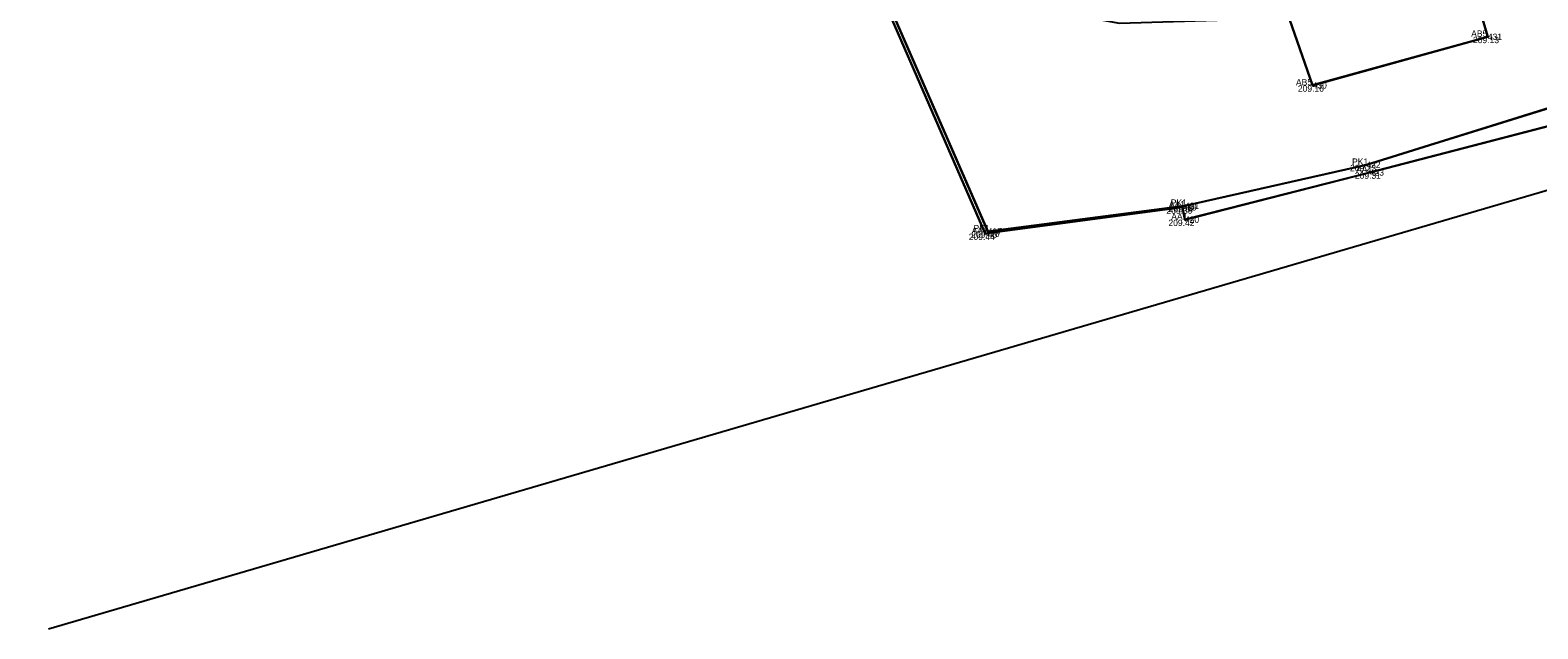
# Model space of a CAD drawing. Extents: x -262982 to -262706, y -1238714 to -1237093.
# Drawn here: x -262858.42 to -262811.08, y -1238714.26 to -1238695.45 of the extents above; entities that cross this region are included whole.
import ezdxf

# ---------------------------------------------------------------- set-up
doc = ezdxf.new("R2010")
doc.units = 0
for name, color, linetype in [('02_Oplotenie', 7, 'Continuous'), ('03_Asfalt', 7, 'Continuous'), ('08_Mimo_zelene', 7, 'Continuous'), ('10', 7, 'Continuous'), ('Groma (21)', 7, 'Continuous'), ('Groma (22)', 7, 'Continuous'), ('Groma (23)', 7, 'Continuous'), ('Groma (24)', 7, 'Continuous'), ('U001_Ostatné_plochy', 7, 'Continuous'), ('U001_Zeleň_mimo', 7, 'Continuous'), ('U001_Zeleň_vnútro', 7, 'Continuous')]:
    doc.layers.add(name, color=color, linetype=linetype)

msp = doc.modelspace()

# ---------------------------------------------------------------- linework, layer by layer
at = {"layer": '02_Oplotenie'}
msp.add_lwpolyline([(-262896.033, -1238537.323), (-262884.611, -1238562.768), (-262875.332, -1238581.932), (-262871.26, -1238591.133), (-262867.507, -1238600.089), (-262859.113, -1238621.74), (-262850.323, -1238645.054), (-262841.974, -1238667.148), (-262839.469, -1238673.878), (-262839.26, -1238674.43), (-262837.725, -1238678.482), (-262834.801, -1238686.521), (-262833.14, -1238690.761), (-262828.35, -1238701.769), (-262822.156, -1238700.967), (-262816.462, -1238699.68), (-262807.77, -1238696.972), (-262807.339, -1238690.207)], dxfattribs=at)
at = {"layer": '03_Asfalt'}
msp.add_lwpolyline([(-262881.2, -1238585.494), (-262874.644, -1238603.324), (-262866.886, -1238624.256), (-262857.388, -1238650.091), (-262854.721, -1238649.057), (-262851.25, -1238656.85), (-262845.959, -1238668.452), (-262837.314, -1238687.515), (-262834.926, -1238686.561), (-262833.211, -1238690.828), (-262828.426, -1238701.842), (-262822.233, -1238701.015), (-262822.159, -1238701.403), (-262816.354, -1238699.919), (-262807.207, -1238697.538), (-262805.6, -1238694.487), (-262805.937, -1238690.489), (-262804.465, -1238690.033), (-262818.631, -1238655.736), (-262826.695, -1238636.389), (-262836.855, -1238611.872), (-262842.406, -1238598.306), (-262850.452, -1238578.707)], dxfattribs=at)
at = {"layer": '08_Mimo_zelene'}
msp.add_lwpolyline([(-262817.803, -1238678.214), (-262819.181, -1238678.564), (-262819.376, -1238678.614), (-262820.948, -1238679.013), (-262821.555, -1238690.42), (-262821.486, -1238690.803), (-262821.464, -1238691.979), (-262821.612, -1238692.34), (-262819.863, -1238691.866), (-262819.273, -1238693.95), (-262818.147, -1238697.183), (-262812.645, -1238695.656), (-262813.715, -1238692.011)], close=True, dxfattribs=at)
at = {"layer": '10'}
msp.add_line((-262857.845, -1238714.263), (-262769.355, -1238688.329), dxfattribs=at)
at = {"layer": 'Groma (21)'}
for centre in [(-262812.645, -1238695.656), (-262818.147, -1238697.183), (-262816.462, -1238699.68), (-262816.354, -1238699.919), (-262822.233, -1238701.015), (-262822.156, -1238700.967), (-262822.159, -1238701.403), (-262828.426, -1238701.842), (-262828.35, -1238701.769)]:
    msp.add_circle(centre, 0.01, dxfattribs=at)
at = {"layer": 'U001_Ostatné_plochy'}
msp.add_lwpolyline([(-262818.15, -1238697.18), (-262819.27, -1238693.95), (-262819.86, -1238691.87), (-262821.61, -1238692.34), (-262821.46, -1238691.98), (-262821.49, -1238690.8), (-262821.56, -1238690.42), (-262820.95, -1238679.01), (-262819.38, -1238678.61), (-262819.18, -1238678.56), (-262817.8, -1238678.21), (-262813.72, -1238692.01), (-262812.65, -1238695.66)], close=True, dxfattribs=at)
at = {"layer": 'U001_Zeleň_mimo'}
for points in [[(-262850.45, -1238578.71), (-262842.41, -1238598.31), (-262836.86, -1238611.87), (-262826.7, -1238636.39), (-262818.63, -1238655.74), (-262804.47, -1238690.03), (-262805.94, -1238690.49), (-262805.6, -1238694.49), (-262807.21, -1238697.54), (-262816.35, -1238699.92), (-262822.16, -1238701.4), (-262822.23, -1238701.02), (-262828.43, -1238701.84), (-262833.21, -1238690.83), (-262834.93, -1238686.56), (-262837.31, -1238687.52), (-262845.96, -1238668.45), (-262851.25, -1238656.85), (-262854.72, -1238649.06), (-262857.39, -1238650.09), (-262866.89, -1238624.26), (-262874.64, -1238603.32), (-262881.2, -1238585.49)], [(-262850.45, -1238578.71), (-262842.41, -1238598.31), (-262836.86, -1238611.87), (-262826.7, -1238636.39), (-262818.63, -1238655.74), (-262804.47, -1238690.03), (-262805.94, -1238690.49), (-262805.6, -1238694.49), (-262807.21, -1238697.54), (-262816.35, -1238699.92), (-262822.16, -1238701.4), (-262822.23, -1238701.02), (-262828.43, -1238701.84), (-262833.21, -1238690.83), (-262834.93, -1238686.56), (-262837.31, -1238687.52), (-262845.96, -1238668.45), (-262851.25, -1238656.85), (-262854.72, -1238649.06), (-262857.39, -1238650.09), (-262866.89, -1238624.26), (-262874.64, -1238603.32), (-262881.2, -1238585.49)], [(-262850.32, -1238645.05), (-262841.97, -1238667.15), (-262839.47, -1238673.88), (-262839.26, -1238674.43), (-262837.72, -1238678.48), (-262834.8, -1238686.52), (-262833.14, -1238690.76), (-262828.35, -1238701.77), (-262822.16, -1238700.97), (-262816.46, -1238699.68), (-262807.77, -1238696.97), (-262807.34, -1238690.21), (-262818.53, -1238674.84), (-262818.69, -1238673.95), (-262819.78, -1238666.25), (-262819.69, -1238665.25), (-262822.28, -1238657.84)]]:
    msp.add_lwpolyline(points, dxfattribs=at)
at = {"layer": 'U001_Zeleň_vnútro'}
for points in [[(-262807.77, -1238696.97), (-262816.46, -1238699.68), (-262822.16, -1238700.97), (-262828.35, -1238701.77), (-262833.14, -1238690.76), (-262834.8, -1238686.52), (-262837.72, -1238678.48), (-262839.26, -1238674.43), (-262839.47, -1238673.88), (-262841.97, -1238667.15), (-262850.32, -1238645.05)], [(-262849.25, -1238645.17), (-262840.95, -1238666.78), (-262838.63, -1238673.56), (-262837.73, -1238674.66), (-262836.74, -1238677.38), (-262836.91, -1238678.37), (-262831.83, -1238691.77), (-262830.27, -1238693.55), (-262829.67, -1238693.92), (-262827.76, -1238694.54), (-262827.28, -1238694.67), (-262824.21, -1238695.23), (-262821.16, -1238695.13), (-262820.85, -1238694.95), (-262819.27, -1238693.95), (-262818.15, -1238697.18), (-262812.65, -1238695.66), (-262813.72, -1238692.01), (-262817.8, -1238678.21), (-262818.53, -1238674.84), (-262807.34, -1238690.21)]]:
    msp.add_lwpolyline(points, dxfattribs=at)

# ---------------------------------------------------------------- texts
at = {"layer": 'Groma (22)'}
for s, p in [('431', (-262812.645, -1238695.756)), ('430', (-262818.147, -1238697.283)), ('422', (-262816.462, -1238699.78)), ('423', (-262816.354, -1238700.019)), ('419', (-262822.233, -1238701.115)), ('421', (-262822.156, -1238701.067)), ('420', (-262822.159, -1238701.503)), ('418', (-262828.426, -1238701.942)), ('417', (-262828.35, -1238701.869))]:
    msp.add_text(s, height=0.2, dxfattribs=at).set_placement(p)
at = {"layer": 'Groma (23)'}
for s, p in [('209.13', (-262813.113, -1238695.856)), ('209.16', (-262818.611, -1238697.383)), ('209.23', (-262816.974, -1238699.88)), ('209.31', (-262816.822, -1238700.119)), ('209.39', (-262822.74, -1238701.215)), ('209.37', (-262822.669, -1238701.167)), ('209.42', (-262822.676, -1238701.603)), ('209.44', (-262828.947, -1238702.042)), ('209.45', (-262828.867, -1238701.969))]:
    msp.add_text(s, height=0.2, dxfattribs=at).set_placement(p)
at = {"layer": 'Groma (24)'}
for s, p in [('AB5', (-262813.169, -1238695.656)), ('AB5', (-262818.671, -1238697.183)), ('PK1', (-262816.909, -1238699.68)), ('AA1', (-262816.782, -1238699.919)), ('AA1', (-262822.661, -1238701.015)), ('PK1', (-262822.603, -1238700.967)), ('PK1', (-262828.797, -1238701.769)), ('AA1', (-262822.587, -1238701.403)), ('AA1', (-262828.854, -1238701.842))]:
    msp.add_text(s, height=0.2, dxfattribs=at).set_placement(p)

doc.saveas('drawing.dxf')
